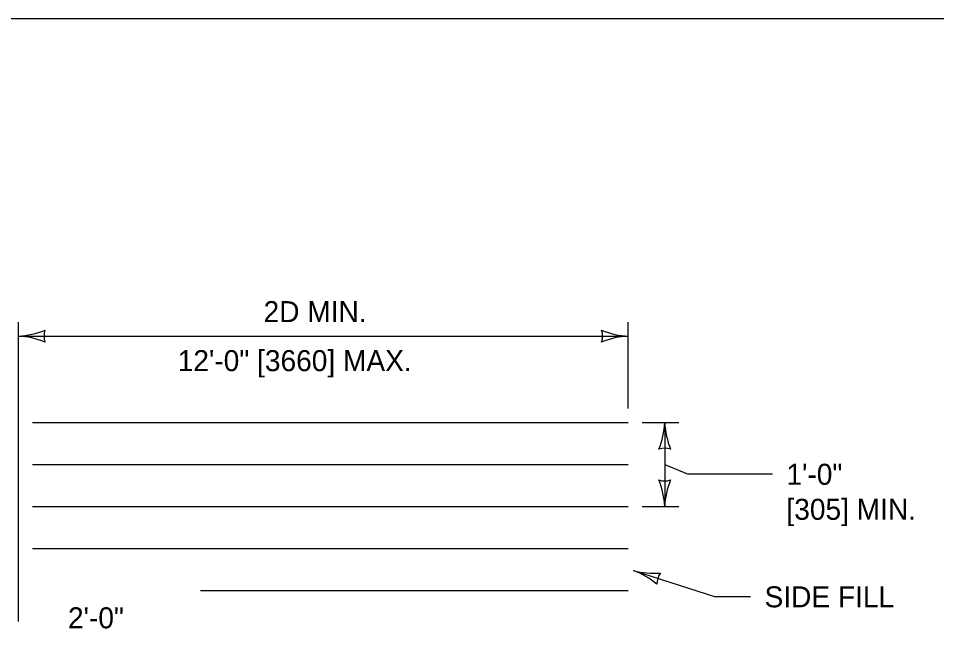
# Model space of a CAD drawing. Extents: x 49991.4 to 50021, y 49987.6 to 50011.4.
# Drawn here: x 50003.835 to 50006.457, y 49997.25 to 49998.999 of the extents above; entities that cross this region are included whole.
import ezdxf

# ---------------------------------------------------------------- set-up
doc = ezdxf.new("R2010")
doc.units = 0
for name, color, linetype in [('Level 1', 7, 'Continuous'), ('Level 2', 7, 'Continuous'), ('Level 3', 7, 'Continuous')]:
    doc.layers.add(name, color=color, linetype=linetype)

msp = doc.modelspace()

# ---------------------------------------------------------------- linework, layer by layer
at = {"layer": 'Level 1'}
for p, q in [((50003.875, 49997.8446), (50005.5768, 49997.8446)), ((50003.875, 49997.7246), (50005.5768, 49997.7246)), ((50003.875, 49997.6046), (50005.5768, 49997.6046)), ((50003.875, 49997.4846), (50005.5768, 49997.4846)), ((50004.355, 49997.3646), (50005.5768, 49997.3646))]:
    msp.add_line(p, q, dxfattribs=at)
msp.add_lwpolyline([(49999.3835, 49998.9992), (50016.7501, 49998.9992), (50016.7501, 49987.7988), (49999.3835, 49987.7988)], close=True, dxfattribs=at)
at = {"layer": 'Level 3'}
for p, q in [((50003.835, 49997.2769), (50003.835, 49998.1315)), ((50005.5768, 49997.8846), (50005.5768, 49998.1315)), ((50003.835, 49998.0915), (50005.5768, 49998.0915)), ((50005.6168, 49997.8446), (50005.7208, 49997.8446)), ((50005.6168, 49997.8446), (50005.7208, 49997.8446)), ((50005.6808, 49997.8446), (50005.6808, 49997.6046)), ((50005.6808, 49997.7246), (50005.7477, 49997.6969)), ((50005.9885, 49997.6969), (50005.7477, 49997.6969)), ((50005.6168, 49997.6046), (50005.7208, 49997.6046)), ((50005.6168, 49997.6046), (50005.7208, 49997.6046)), ((50005.5914, 49997.422), (50005.826, 49997.3469)), ((50005.926, 49997.3469), (50005.826, 49997.3469))]:
    msp.add_line(p, q, dxfattribs=at)
for centre, radius, start, end in [((50003.8235, 49998.3242), 0.233, 272.8273, 292.0772), ((50003.8258, 49997.8694), 0.2223, 67.456, 87.6395), ((50003.9632, 49998.0915), 0.0548, 162.1388, 197.8612), ((50005.586, 49998.3136), 0.2223, 247.456, 267.6395), ((50005.4486, 49998.0915), 0.0548, 342.1388, 17.8612), ((50005.5883, 49997.8588), 0.233, 92.8273, 112.0772), ((50005.4587, 49997.8538), 0.2223, 337.456, 357.6395), ((50005.4587, 49997.8538), 0.2223, 337.456, 357.6395), ((50005.9136, 49997.8561), 0.233, 182.8273, 202.0772), ((50005.9136, 49997.8561), 0.233, 182.8273, 202.0772), ((50005.6808, 49997.7164), 0.0548, 72.1388, 107.8612), ((50005.6808, 49997.7164), 0.0548, 72.1388, 107.8612), ((50005.6808, 49997.7328), 0.0548, 252.1388, 287.8612), ((50005.4481, 49997.5931), 0.233, 2.8273, 22.0772), ((50005.6808, 49997.7328), 0.0548, 252.1388, 287.8612), ((50005.4481, 49997.5931), 0.233, 2.8273, 22.0772), ((50005.903, 49997.5954), 0.2223, 157.456, 177.6395), ((50005.903, 49997.5954), 0.2223, 157.456, 177.6395), ((50005.5149, 49997.2132), 0.2223, 49.708, 69.8915), ((50005.6514, 49997.6471), 0.233, 255.0793, 274.3291), ((50005.7135, 49997.3829), 0.0548, 144.3908, 180.1131)]:
    msp.add_arc(centre, radius, start, end, dxfattribs=at)

# ---------------------------------------------------------------- texts
at = {"layer": 'Level 2'}
for s, p in [('2D MIN.', (50004.5353, 49998.1315)), ('12\'-0" [3660] MAX.', (50004.2901, 49997.9915)), ('1\'-0" ', (50006.0285, 49997.6669)), ('[305] MIN.', (50006.0285, 49997.5669)), ('SIDE FILL', (50005.966, 49997.3169)), ('2\'-0"', (50003.9767, 49997.2569))]:
    msp.add_text(s, height=0.06, dxfattribs=at).set_placement(p)

doc.saveas('drawing.dxf')
